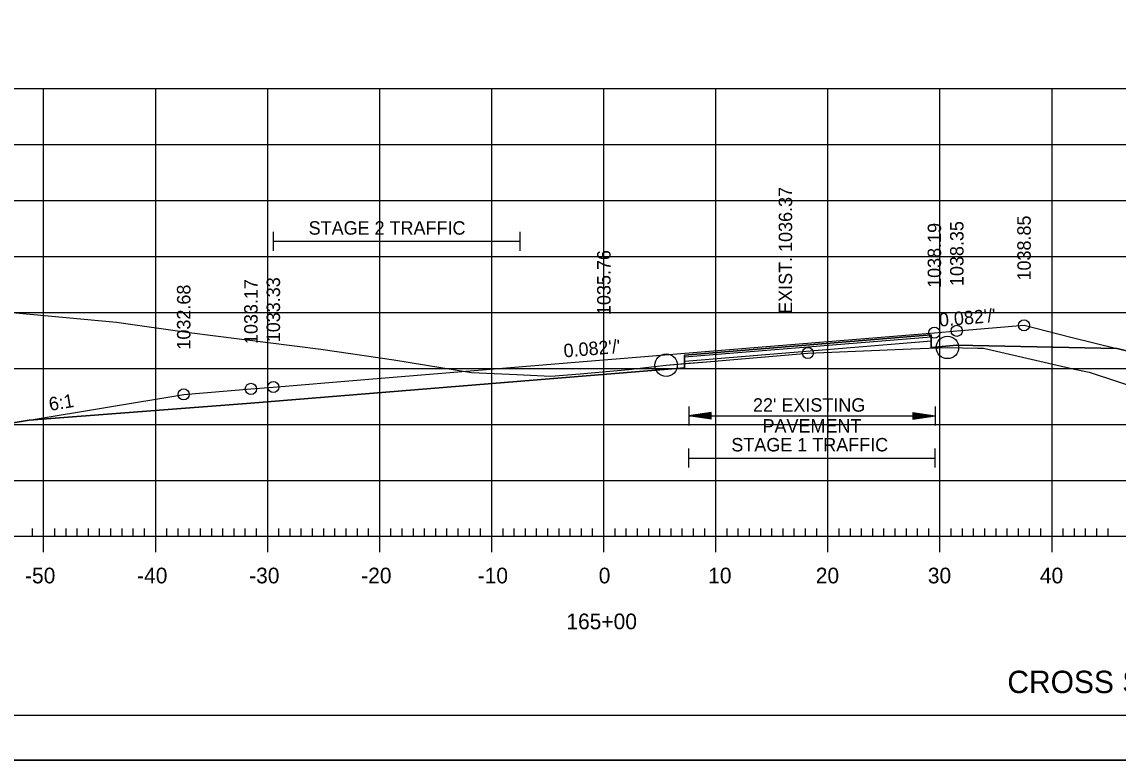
# Model space of a CAD drawing. Extents: x 1322838 to 1324533, y 339903 to 351025.
# Drawn here: x 1323691.8 to 1323789.6, y 346255.3 to 346321.2 of the extents above; entities that cross this region are included whole.
import ezdxf

# ---------------------------------------------------------------- set-up
doc = ezdxf.new("R2010")
doc.units = 0
for name, color, linetype in [('R_Alt Surface', 7, 'Continuous'), ('R_Axis', 7, 'Continuous'), ('R_Axis Annot', 7, 'Continuous'), ('R_Border', 7, 'Continuous'), ('R_Draft', 7, 'Continuous'), ('R_Exist Surface', 7, 'Continuous'), ('R_Fin Surface', 7, 'Continuous'), ('R_Fin Surface Annot', 7, 'Continuous'), ('R_Grid', 7, 'Continuous'), ('R_No Plot', 7, 'Continuous'), ('R_Xsect Elev', 7, 'Continuous')]:
    doc.layers.add(name, color=color, linetype=linetype)

msp = doc.modelspace()

# ---------------------------------------------------------------- linework, layer by layer
at = {"layer": 'R_Alt Surface'}
msp.add_lwpolyline([(1323692.433, 346285.672), (1323712.216, 346287.171), (1323750.905, 346290.353), (1323750.915, 346291.478), (1323772.924, 346293.289), (1323772.935, 346292.164), (1323775.215, 346292.352), (1323789.504, 346292.066)], dxfattribs=at)
at = {"layer": 'R_Axis'}
for p, q in [((1323692.715, 346275.292), (1323692.715, 346275.992)), ((1323693.715, 346273.892), (1323693.715, 346276.692)), ((1323694.715, 346275.292), (1323694.715, 346275.992)), ((1323695.715, 346275.292), (1323695.715, 346275.992)), ((1323696.715, 346275.292), (1323696.715, 346275.992)), ((1323697.715, 346275.292), (1323697.715, 346275.992)), ((1323698.715, 346275.292), (1323698.715, 346275.992)), ((1323699.715, 346275.292), (1323699.715, 346275.992)), ((1323700.715, 346275.292), (1323700.715, 346275.992)), ((1323701.715, 346275.292), (1323701.715, 346275.992)), ((1323702.715, 346275.292), (1323702.715, 346275.992)), ((1323703.715, 346273.892), (1323703.715, 346276.692)), ((1323704.715, 346275.292), (1323704.715, 346275.992)), ((1323705.715, 346275.292), (1323705.715, 346275.992)), ((1323706.715, 346275.292), (1323706.715, 346275.992)), ((1323707.715, 346275.292), (1323707.715, 346275.992)), ((1323708.715, 346275.292), (1323708.715, 346275.992)), ((1323709.715, 346275.292), (1323709.715, 346275.992)), ((1323710.715, 346275.292), (1323710.715, 346275.992)), ((1323711.715, 346275.292), (1323711.715, 346275.992)), ((1323712.715, 346275.292), (1323712.715, 346275.992)), ((1323713.715, 346273.892), (1323713.715, 346276.692)), ((1323714.715, 346275.292), (1323714.715, 346275.992)), ((1323715.715, 346275.292), (1323715.715, 346275.992)), ((1323716.715, 346275.292), (1323716.715, 346275.992)), ((1323717.715, 346275.292), (1323717.715, 346275.992)), ((1323718.715, 346275.292), (1323718.715, 346275.992)), ((1323719.715, 346275.292), (1323719.715, 346275.992)), ((1323720.715, 346275.292), (1323720.715, 346275.992)), ((1323721.715, 346275.292), (1323721.715, 346275.992)), ((1323722.715, 346275.292), (1323722.715, 346275.992)), ((1323723.715, 346273.892), (1323723.715, 346276.692)), ((1323724.715, 346275.292), (1323724.715, 346275.992)), ((1323725.715, 346275.292), (1323725.715, 346275.992)), ((1323726.715, 346275.292), (1323726.715, 346275.992)), ((1323727.715, 346275.292), (1323727.715, 346275.992)), ((1323728.715, 346275.292), (1323728.715, 346275.992)), ((1323729.715, 346275.292), (1323729.715, 346275.992)), ((1323730.715, 346275.292), (1323730.715, 346275.992)), ((1323731.715, 346275.292), (1323731.715, 346275.992)), ((1323732.715, 346275.292), (1323732.715, 346275.992)), ((1323733.715, 346273.892), (1323733.715, 346276.692)), ((1323734.715, 346275.292), (1323734.715, 346275.992)), ((1323735.715, 346275.292), (1323735.715, 346275.992)), ((1323736.715, 346275.292), (1323736.715, 346275.992)), ((1323737.715, 346275.292), (1323737.715, 346275.992)), ((1323738.715, 346275.292), (1323738.715, 346275.992)), ((1323739.715, 346275.292), (1323739.715, 346275.992)), ((1323740.715, 346275.292), (1323740.715, 346275.992)), ((1323741.715, 346275.292), (1323741.715, 346275.992)), ((1323742.715, 346275.292), (1323742.715, 346275.992)), ((1323743.715, 346273.892), (1323743.715, 346276.692)), ((1323744.715, 346275.292), (1323744.715, 346275.992)), ((1323745.715, 346275.292), (1323745.715, 346275.992)), ((1323746.715, 346275.292), (1323746.715, 346275.992)), ((1323747.715, 346275.292), (1323747.715, 346275.992)), ((1323748.715, 346275.292), (1323748.715, 346275.992)), ((1323749.715, 346275.292), (1323749.715, 346275.992)), ((1323750.715, 346275.292), (1323750.715, 346275.992)), ((1323751.715, 346275.292), (1323751.715, 346275.992)), ((1323752.715, 346275.292), (1323752.715, 346275.992)), ((1323753.715, 346273.892), (1323753.715, 346276.692)), ((1323754.715, 346275.292), (1323754.715, 346275.992)), ((1323755.715, 346275.292), (1323755.715, 346275.992)), ((1323756.715, 346275.292), (1323756.715, 346275.992)), ((1323757.715, 346275.292), (1323757.715, 346275.992)), ((1323758.715, 346275.292), (1323758.715, 346275.992)), ((1323759.715, 346275.292), (1323759.715, 346275.992)), ((1323760.715, 346275.292), (1323760.715, 346275.992)), ((1323761.715, 346275.292), (1323761.715, 346275.992)), ((1323762.715, 346275.292), (1323762.715, 346275.992)), ((1323763.715, 346273.892), (1323763.715, 346276.692)), ((1323764.715, 346275.292), (1323764.715, 346275.992)), ((1323765.715, 346275.292), (1323765.715, 346275.992)), ((1323766.715, 346275.292), (1323766.715, 346275.992)), ((1323767.715, 346275.292), (1323767.715, 346275.992)), ((1323768.715, 346275.292), (1323768.715, 346275.992)), ((1323769.715, 346275.292), (1323769.715, 346275.992)), ((1323770.715, 346275.292), (1323770.715, 346275.992)), ((1323771.715, 346275.292), (1323771.715, 346275.992)), ((1323772.715, 346275.292), (1323772.715, 346275.992)), ((1323773.715, 346273.892), (1323773.715, 346276.692)), ((1323774.715, 346275.292), (1323774.715, 346275.992)), ((1323775.715, 346275.292), (1323775.715, 346275.992)), ((1323776.715, 346275.292), (1323776.715, 346275.992)), ((1323777.715, 346275.292), (1323777.715, 346275.992)), ((1323778.715, 346275.292), (1323778.715, 346275.992)), ((1323779.715, 346275.292), (1323779.715, 346275.992)), ((1323780.715, 346275.292), (1323780.715, 346275.992)), ((1323781.715, 346275.292), (1323781.715, 346275.992)), ((1323782.715, 346275.292), (1323782.715, 346275.992)), ((1323783.715, 346273.892), (1323783.715, 346276.692)), ((1323784.715, 346275.292), (1323784.715, 346275.992)), ((1323785.715, 346275.292), (1323785.715, 346275.992)), ((1323786.715, 346275.292), (1323786.715, 346275.992)), ((1323787.715, 346275.292), (1323787.715, 346275.992)), ((1323788.715, 346275.292), (1323788.715, 346275.992)), ((1323563.715, 346275.292), (1323843.715, 346275.292))]:
    msp.add_line(p, q, dxfattribs=at)
at = {"layer": 'R_Axis Annot'}
for p, q in [((1323714.215, 346302.494), (1323714.215, 346300.788)), ((1323736.215, 346302.494), (1323736.215, 346300.788)), ((1323714.215, 346301.641), (1323736.215, 346301.641)), ((1323751.292, 346286.901), (1323751.292, 346285.195)), ((1323773.292, 346286.901), (1323773.292, 346285.195)), ((1323753.292, 346286.348), (1323751.292, 346286.048)), ((1323753.292, 346285.748), (1323751.292, 346286.048)), ((1323751.292, 346286.048), (1323773.292, 346286.048)), ((1323753.292, 346286.298), (1323751.626, 346286.048)), ((1323753.292, 346285.798), (1323751.626, 346286.048)), ((1323753.292, 346286.247), (1323751.97, 346286.048)), ((1323753.292, 346285.849), (1323751.97, 346286.048)), ((1323753.292, 346286.197), (1323752.303, 346286.048)), ((1323753.292, 346285.899), (1323752.303, 346286.048)), ((1323753.292, 346286.146), (1323752.642, 346286.048)), ((1323753.292, 346285.951), (1323752.642, 346286.048)), ((1323753.292, 346286.095), (1323752.976, 346286.048)), ((1323753.292, 346286.001), (1323752.976, 346286.048)), ((1323753.292, 346285.748), (1323753.292, 346286.348)), ((1323771.292, 346286.348), (1323773.292, 346286.048)), ((1323771.292, 346286.348), (1323771.292, 346285.748)), ((1323771.292, 346286.298), (1323772.958, 346286.048)), ((1323771.292, 346286.247), (1323772.614, 346286.048)), ((1323771.292, 346286.197), (1323772.281, 346286.048)), ((1323771.292, 346286.145), (1323771.942, 346286.048)), ((1323771.292, 346286.095), (1323771.608, 346286.048)), ((1323771.292, 346285.748), (1323773.292, 346286.048)), ((1323771.292, 346285.95), (1323771.942, 346286.048)), ((1323771.292, 346285.849), (1323772.614, 346286.048)), ((1323771.292, 346285.798), (1323772.958, 346286.048)), ((1323771.292, 346285.899), (1323772.281, 346286.048)), ((1323771.292, 346286.001), (1323771.608, 346286.048)), ((1323751.26, 346283.136), (1323751.26, 346281.43)), ((1323773.26, 346283.136), (1323773.26, 346281.43)), ((1323751.26, 346282.283), (1323773.26, 346282.283))]:
    msp.add_line(p, q, dxfattribs=at)
at = {"layer": 'R_Border'}
msp.add_line((1323861.895, 346259.292), (1323545.715, 346259.292), dxfattribs=at)
at = {"layer": 'R_Exist Surface'}
msp.add_lwpolyline([(1323668.418, 346297.352), (1323700.212, 346294.414), (1323706.693, 346293.506), (1323718.468, 346292.011), (1323724.96, 346291.064), (1323731.898, 346289.913), (1323735.962, 346289.747), (1323738.974, 346289.591), (1323741.589, 346289.801), (1323745.92, 346290.19), (1323748.238, 346290.457), (1323749.27, 346290.579), (1323753.228, 346290.912), (1323761.92, 346291.663), (1323771.148, 346292.03), (1323774.379, 346292.161), (1323777.052, 346292.093), (1323777.605, 346292.082), (1323785.714, 346290.224), (1323787.019, 346289.945), (1323797.335, 346286.557)], dxfattribs=at)
at = {"layer": 'R_Fin Surface'}
msp.add_lwpolyline([(1323635.417, 346300.569), (1323635.419, 346300.568), (1323635.42, 346300.568), (1323636.677, 346300.149), (1323684.215, 346284.303), (1323692.433, 346285.672), (1323706.216, 346287.969), (1323712.215, 346288.463), (1323714.215, 346288.627), (1323722.019, 346289.269), (1323743.686, 346291.051), (1323743.715, 346291.054), (1323756.379, 346292.095), (1323773.215, 346293.48), (1323773.216, 346293.48), (1323775.215, 346293.644), (1323781.216, 346294.138), (1323785.396, 346293.093), (1323789.5, 346292.067), (1323789.519, 346292.062), (1323794.531, 346290.809), (1323803.215, 346288.638), (1323809.418, 346286.57), (1323812.464, 346285.555)], dxfattribs=at)
at = {"layer": 'R_Grid'}
for p, q in [((1323563.715, 346315.292), (1323843.715, 346315.292)), ((1323693.715, 346275.292), (1323693.715, 346315.292)), ((1323703.715, 346275.292), (1323703.715, 346315.292)), ((1323713.715, 346275.292), (1323713.715, 346315.292)), ((1323723.715, 346275.292), (1323723.715, 346315.292)), ((1323733.715, 346275.292), (1323733.715, 346315.292)), ((1323743.715, 346275.292), (1323743.715, 346315.292)), ((1323753.715, 346275.292), (1323753.715, 346315.292)), ((1323763.715, 346275.292), (1323763.715, 346315.292)), ((1323773.715, 346275.292), (1323773.715, 346315.292)), ((1323783.715, 346275.292), (1323783.715, 346315.292)), ((1323563.715, 346310.292), (1323843.715, 346310.292)), ((1323563.715, 346305.292), (1323843.715, 346305.292)), ((1323563.715, 346300.292), (1323843.715, 346300.292)), ((1323563.715, 346295.292), (1323843.715, 346295.292)), ((1323563.715, 346290.292), (1323843.715, 346290.292)), ((1323563.715, 346285.292), (1323843.715, 346285.292)), ((1323563.715, 346280.292), (1323843.715, 346280.292)), ((1323563.715, 346275.292), (1323843.715, 346275.292))]:
    msp.add_line(p, q, dxfattribs=at)
at = {"layer": 'R_No Plot'}
for p, q in [((1323750.944, 346290.937), (1323772.957, 346292.748)), ((1323533.315, 346255.313), (1323866.648, 346255.313))]:
    msp.add_line(p, q, dxfattribs=at)
for points in [[(1323533.308, 346468.646), (1323866.648, 346468.646), (1323866.648, 346255.309), (1323533.308, 346255.309)], [(1323779.635, 346464.752), (1323799.255, 346464.752), (1323799.255, 346454.872), (1323815.368, 346454.872), (1323838.567, 346454.872), (1323838.567, 346422.201), (1323861.775, 346422.201), (1323861.895, 346259.292), (1323545.715, 346259.292), (1323545.715, 346464.752)], [(1323635.417, 346300.569), (1323668.418, 346297.352), (1323700.212, 346294.414), (1323706.693, 346293.506), (1323718.468, 346292.011), (1323724.96, 346291.064), (1323731.898, 346289.913), (1323735.962, 346289.747), (1323738.974, 346289.591), (1323741.589, 346289.801), (1323745.92, 346290.19), (1323748.238, 346290.457), (1323749.27, 346290.579), (1323750.908, 346290.717), (1323750.905, 346290.353), (1323712.216, 346287.171), (1323692.433, 346285.672), (1323684.215, 346284.303), (1323636.677, 346300.149), (1323635.419, 346300.568)], [(1323750.908, 346290.717), (1323753.228, 346290.912), (1323761.92, 346291.663), (1323771.148, 346292.03), (1323774.379, 346292.161), (1323777.052, 346292.093), (1323777.605, 346292.082), (1323785.714, 346290.224), (1323787.019, 346289.945), (1323797.335, 346286.557), (1323797.994, 346286.342), (1323798.481, 346286.311), (1323807.621, 346285.665), (1323812.464, 346285.555), (1323809.418, 346286.57), (1323803.215, 346288.638), (1323794.531, 346290.809), (1323789.519, 346292.062), (1323789.504, 346292.066), (1323775.215, 346292.352), (1323772.935, 346292.164), (1323772.924, 346293.289), (1323750.915, 346291.478)]]:
    msp.add_lwpolyline(points, close=True, dxfattribs=at)
msp.add_lwpolyline([(1323750.913, 346291.31), (1323772.926, 346293.122)], dxfattribs=at)
for centre, radius in [((1323781.216, 346294.138), 0.5), ((1323773.216, 346293.48), 0.5), ((1323775.215, 346293.644), 0.5), ((1323774.379, 346292.161), 1), ((1323749.27, 346290.579), 1), ((1323761.92, 346291.663), 0.5), ((1323712.215, 346288.463), 0.5), ((1323714.215, 346288.627), 0.5), ((1323706.216, 346287.969), 0.5)]:
    msp.add_circle(centre, radius, dxfattribs=at)

# ---------------------------------------------------------------- texts
at = {"layer": 'R_Axis Annot'}
for s, height, p in [('STAGE 2 TRAFFIC', 1.2, (1323717.368, 346302.232)), ("22' EXISTING ", 1.2, (1323757.024, 346286.423)), ('PAVEMENT', 1.2, (1323757.875, 346284.557)), ('STAGE 1 TRAFFIC', 1.2, (1323755.093, 346282.874)), ('-50', 1.4, (1323692.056, 346271.092)), ('-40', 1.4, (1323702.056, 346271.092)), ('-30', 1.4, (1323712.056, 346271.092)), ('-20', 1.4, (1323722.056, 346271.092)), ('-10', 1.4, (1323732.453, 346271.092)), ('0', 1.4, (1323743.258, 346271.092)), ('10', 1.4, (1323753.026, 346271.092)), ('20', 1.4, (1323762.63, 346271.092)), ('30', 1.4, (1323772.63, 346271.092)), ('40', 1.4, (1323782.63, 346271.092)), ('165+00', 1.4, (1323740.37, 346266.992))]:
    msp.add_text(s, height=height, dxfattribs=at).set_placement(p)
at = {"layer": 'R_Draft'}
msp.add_text('CROSS SECTION STA. 165+00 TO STA. 166+00', height=2, dxfattribs=at).set_placement((1323779.727, 346261.292))
at = {"layer": 'R_Fin Surface Annot'}
for s, rotation, p in [('1038.35', 90, (1323775.815, 346297.644)), ('1038.85', 90, (1323781.816, 346298.138)), ('1038.19', 90, (1323773.816, 346297.48)), ('1035.76', 90, (1323744.315, 346295.054)), ('1032.68', 90, (1323706.816, 346291.969)), ('1033.17', 90, (1323712.815, 346292.463)), ('1033.33', 90, (1323714.815, 346292.627)), ("0.082'/'", 4.70218, (1323773.672, 346294.019)), ("0.082'/'", 4.70219, (1323740.172, 346291.263)), ('6:1', 9.46035, (1323694.285, 346286.488))]:
    msp.add_text(s, height=1.2, rotation=rotation, dxfattribs=at).set_placement(p)
at = {"layer": 'R_Xsect Elev'}
msp.add_text('EXIST. 1036.37', height=1.2, rotation=90, dxfattribs=at).set_placement((1323760.52, 346295.163))

doc.saveas('drawing.dxf')
